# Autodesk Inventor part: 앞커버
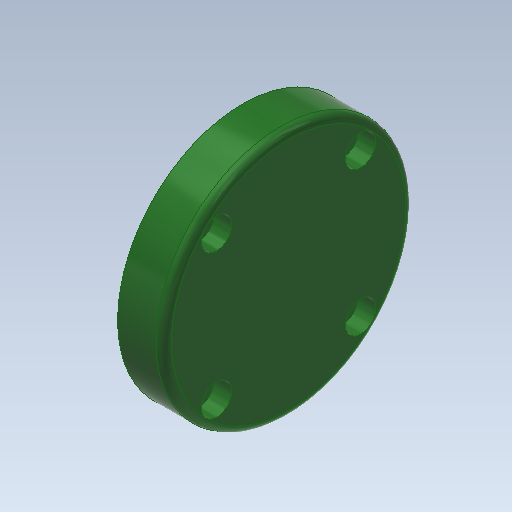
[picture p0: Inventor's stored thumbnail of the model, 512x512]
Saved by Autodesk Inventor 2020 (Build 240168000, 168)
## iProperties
Created: 2015-12
Part Number: 앞커버
Document SubType Name: Modeling
Designer: 앞커버
Density: 2.71 g/cm^3
Mass: 92.3017 g
Surface Area: 115.402 cm^2
Volume: 34.0597 cm^3
Material: 알루미늄-6061
Appearance: 매끄러움 - 짙은 산림 녹색
Company: 한국ATC센터
Author: mdu
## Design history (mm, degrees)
sketch "스케치1"
  geometry: L1 (0, 0)-(17, 0); L2 (17, 0)-(17, 22.5); L3 (17, 22.5)-(12, 22.5); L4 (12, 22.5)-(12, 32.5); L5 (12, 32.5)-(0, 32.5); L6 (0, 32.5)-(0, 0); 1 further point
  constraints: 13 end point, 3 parallel, 2 perpendicular, 1 coincident, 1 horizontal
  dimensions: "d1" = 65 diameter of L5 L1; "d2" = 45 diameter of L3 L1; "d5" = 12 distance of L4.end L5.end; "d6" = 5 distance of L2.end L3.end
revolve "회전1" sketch "스케치1" stored, may be unused: angle "d7" = 90 deg
sketch "스케치2"
  geometry: L1 (0, 0)-(32.5, 0); L2 (0, 0)-(18.738, 18.738); 1 further point
  constraints: 4 end point, 1 horizontal, 1 horizontal alignment, 1 other
  dimensions: "d8" = 45 deg angle of L1 L2; "d9" = 26.5 distance of L1.start L2.end
hole "구멍1" sketch "스케치2" at (18.738, 18.738) diameter "d10" = 4.5; stored, may be unused: countersink angle "d14" = 90 deg, drill point angle "d16" = 118 deg; dims "d11" = 6, "d12" = 8, "d13" = 4.6, "d15" = 8
fillet "모깎기1" dims "d20" = 2
hole "구멍2" diameter "d23" = 26; stored, may be unused: countersink angle "d27" = 90 deg, drill point angle "d29" = 0 deg; dims "d24" = 6, "d25" = 35, "d26" = 11, "d28" = 14, "d52" = 10, "d54" = 10
chamfer "모따기1" distance "d39" = 1; stored, may be unused: second distance "d40" = 2, angle "d41" = 45 deg
fillet "모깎기5" dims "d48" = 3
fillet "모깎기6" dims "d50" = 0.6
node "솔리드1"
pattern_circular "원형 패턴1" dims angle "d18" = 360 deg
